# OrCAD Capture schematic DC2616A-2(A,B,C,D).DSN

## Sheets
1 PAGE4: size Custom; title: HIGH EFFICIENCY POLYPHASE STEP-DOWN; rev: 2; company: TM
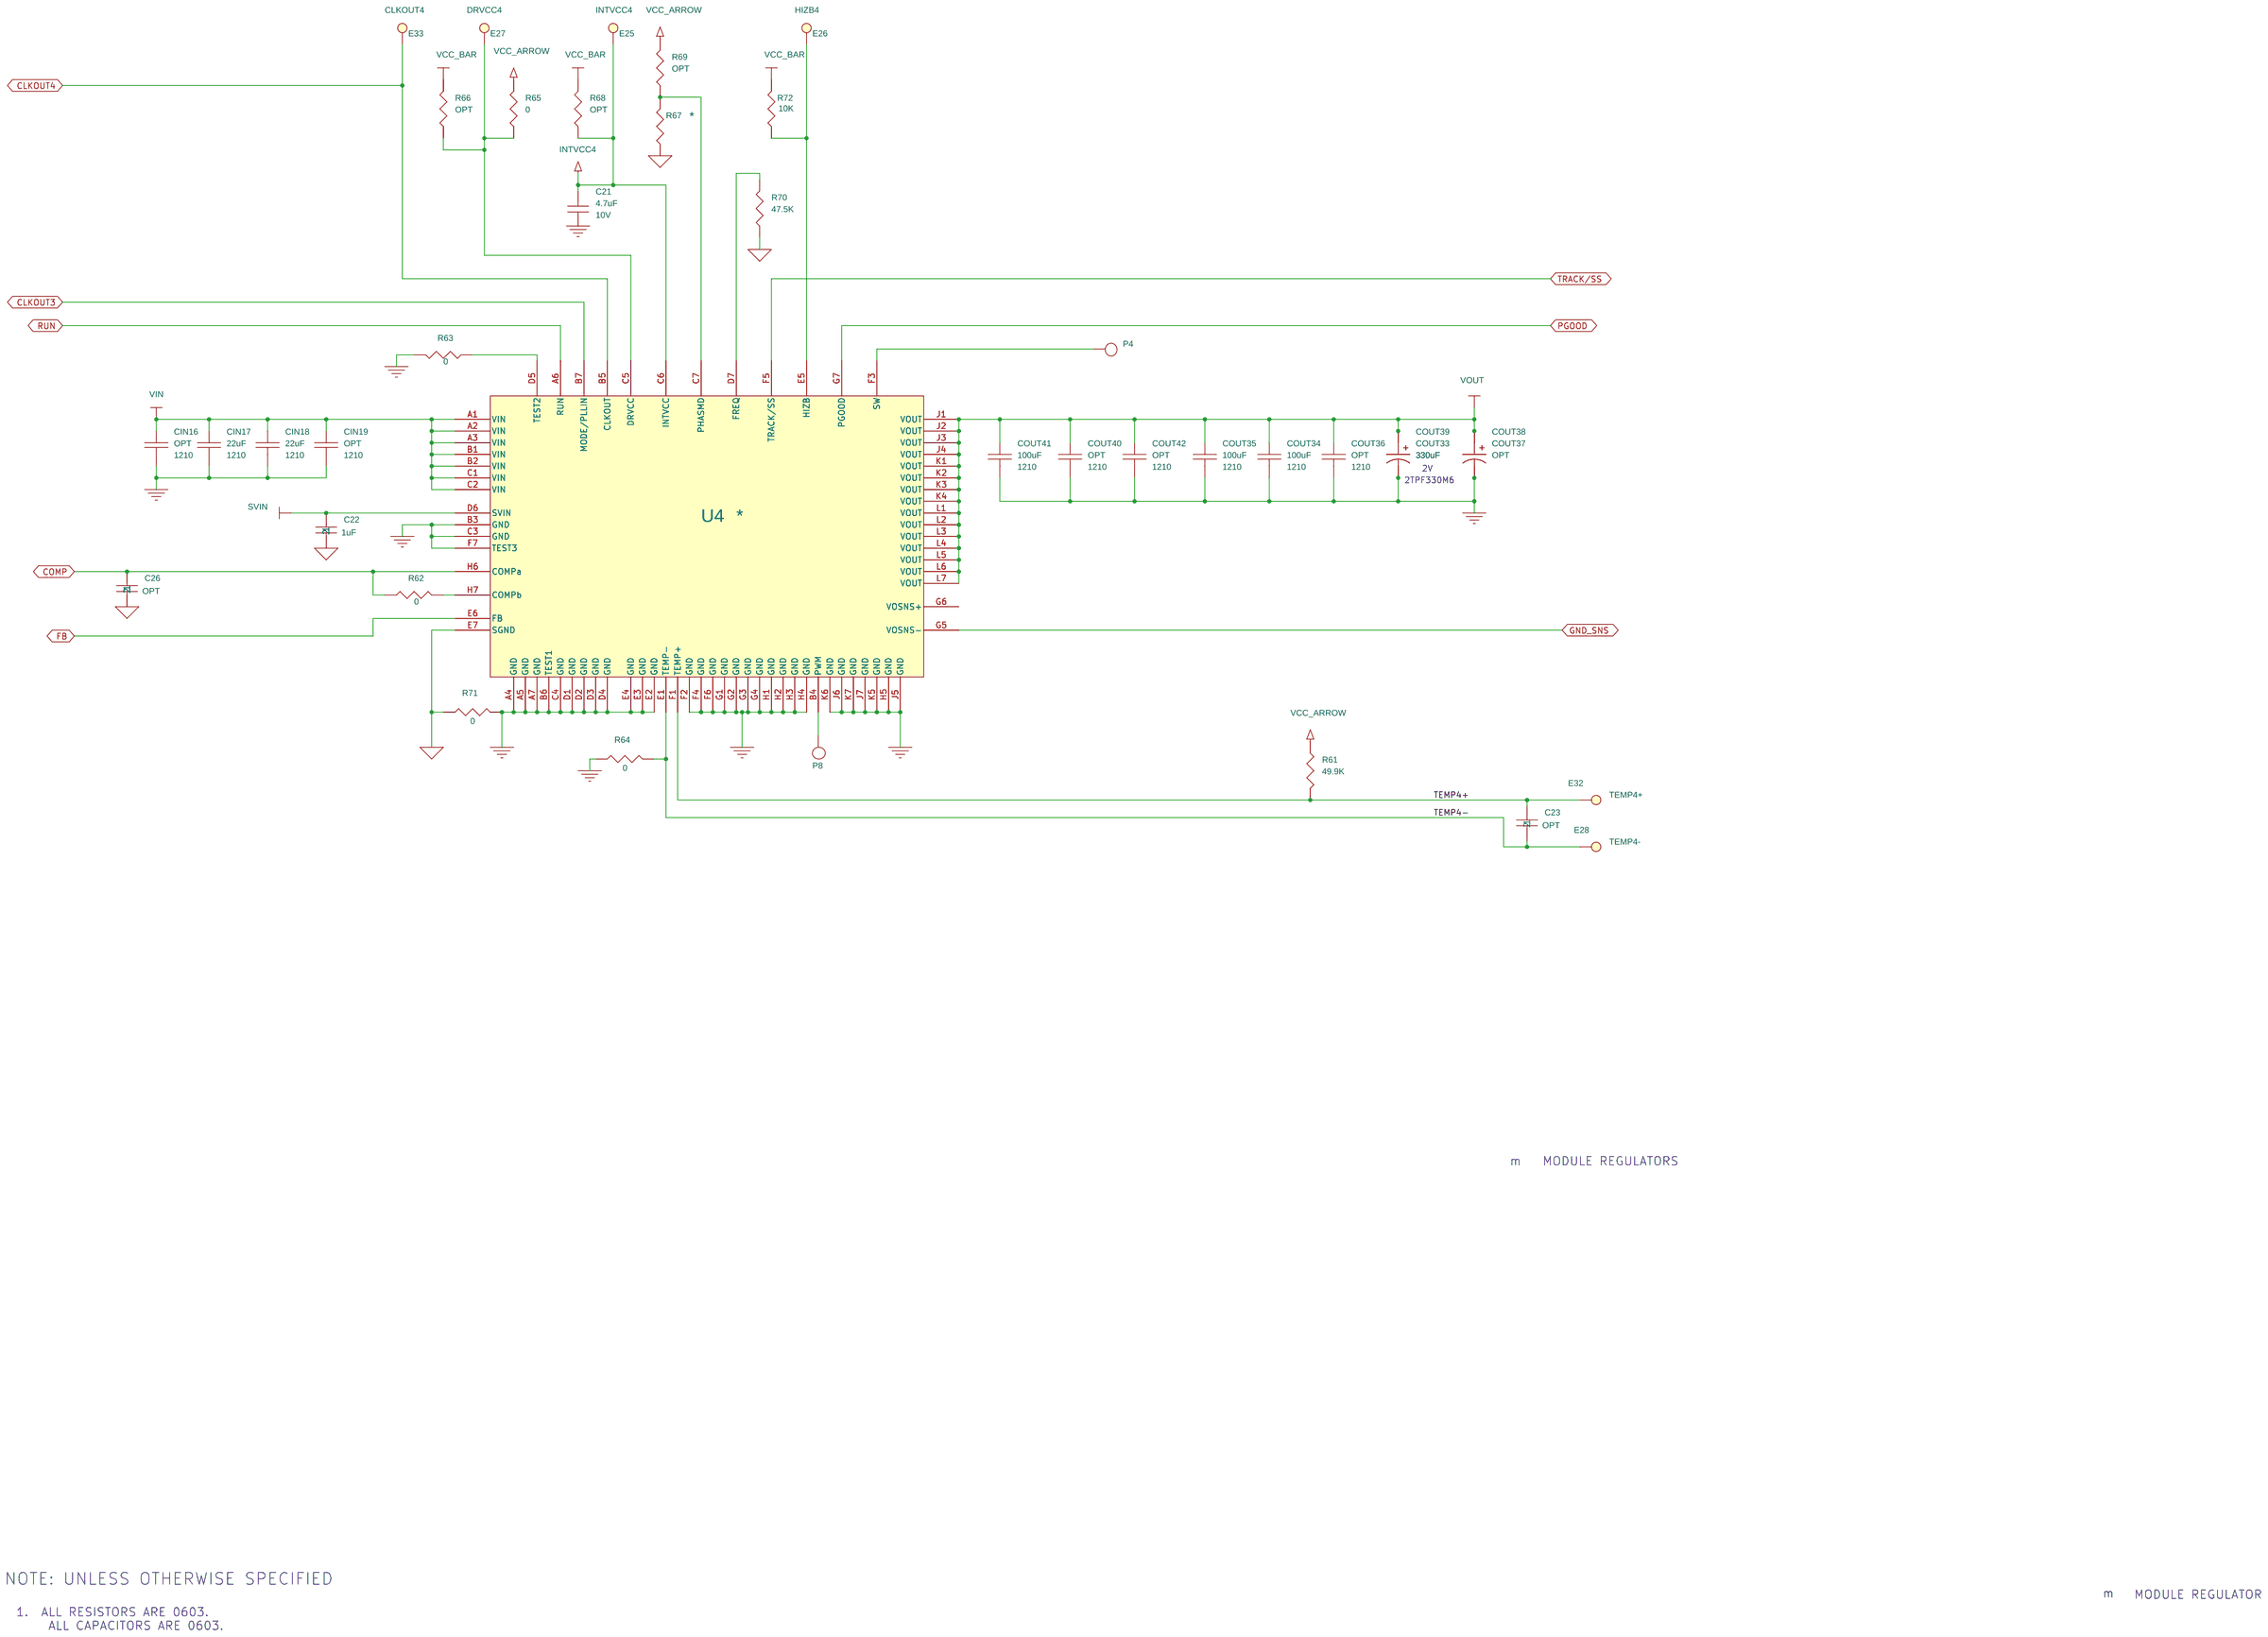
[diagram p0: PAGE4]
2 PAGE3: size Custom
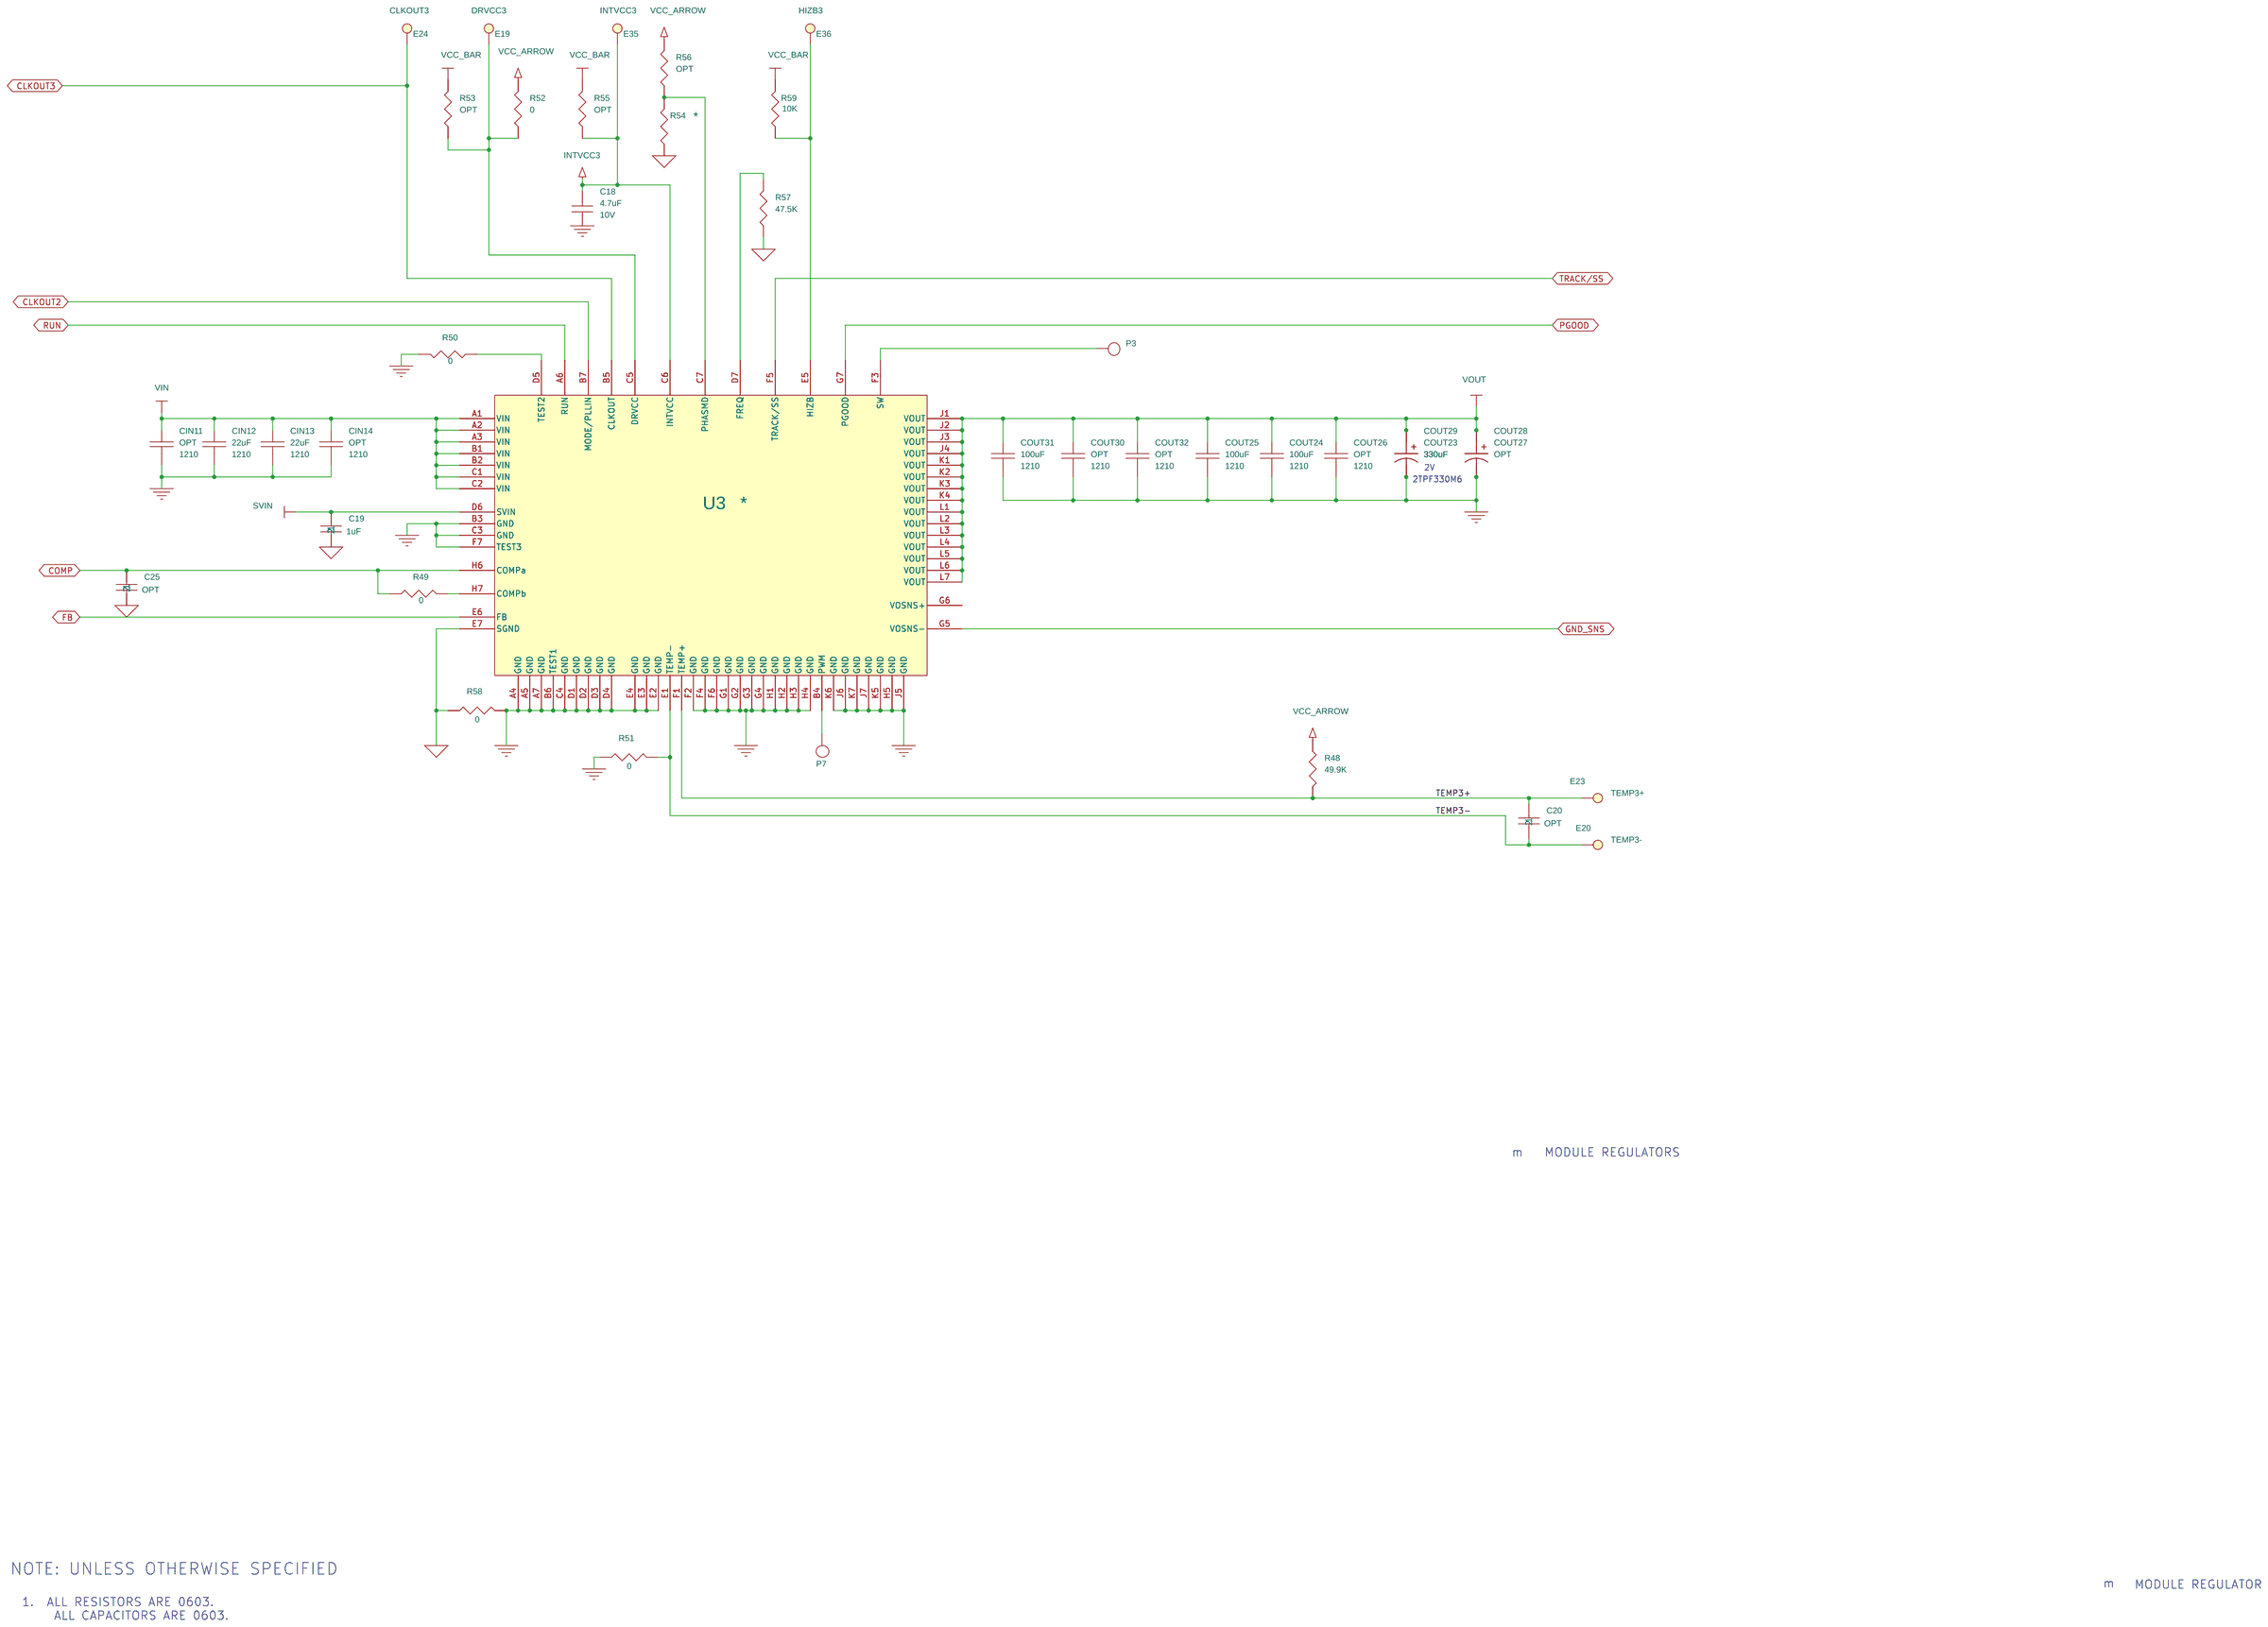
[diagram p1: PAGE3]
3 PAGE2: size Custom
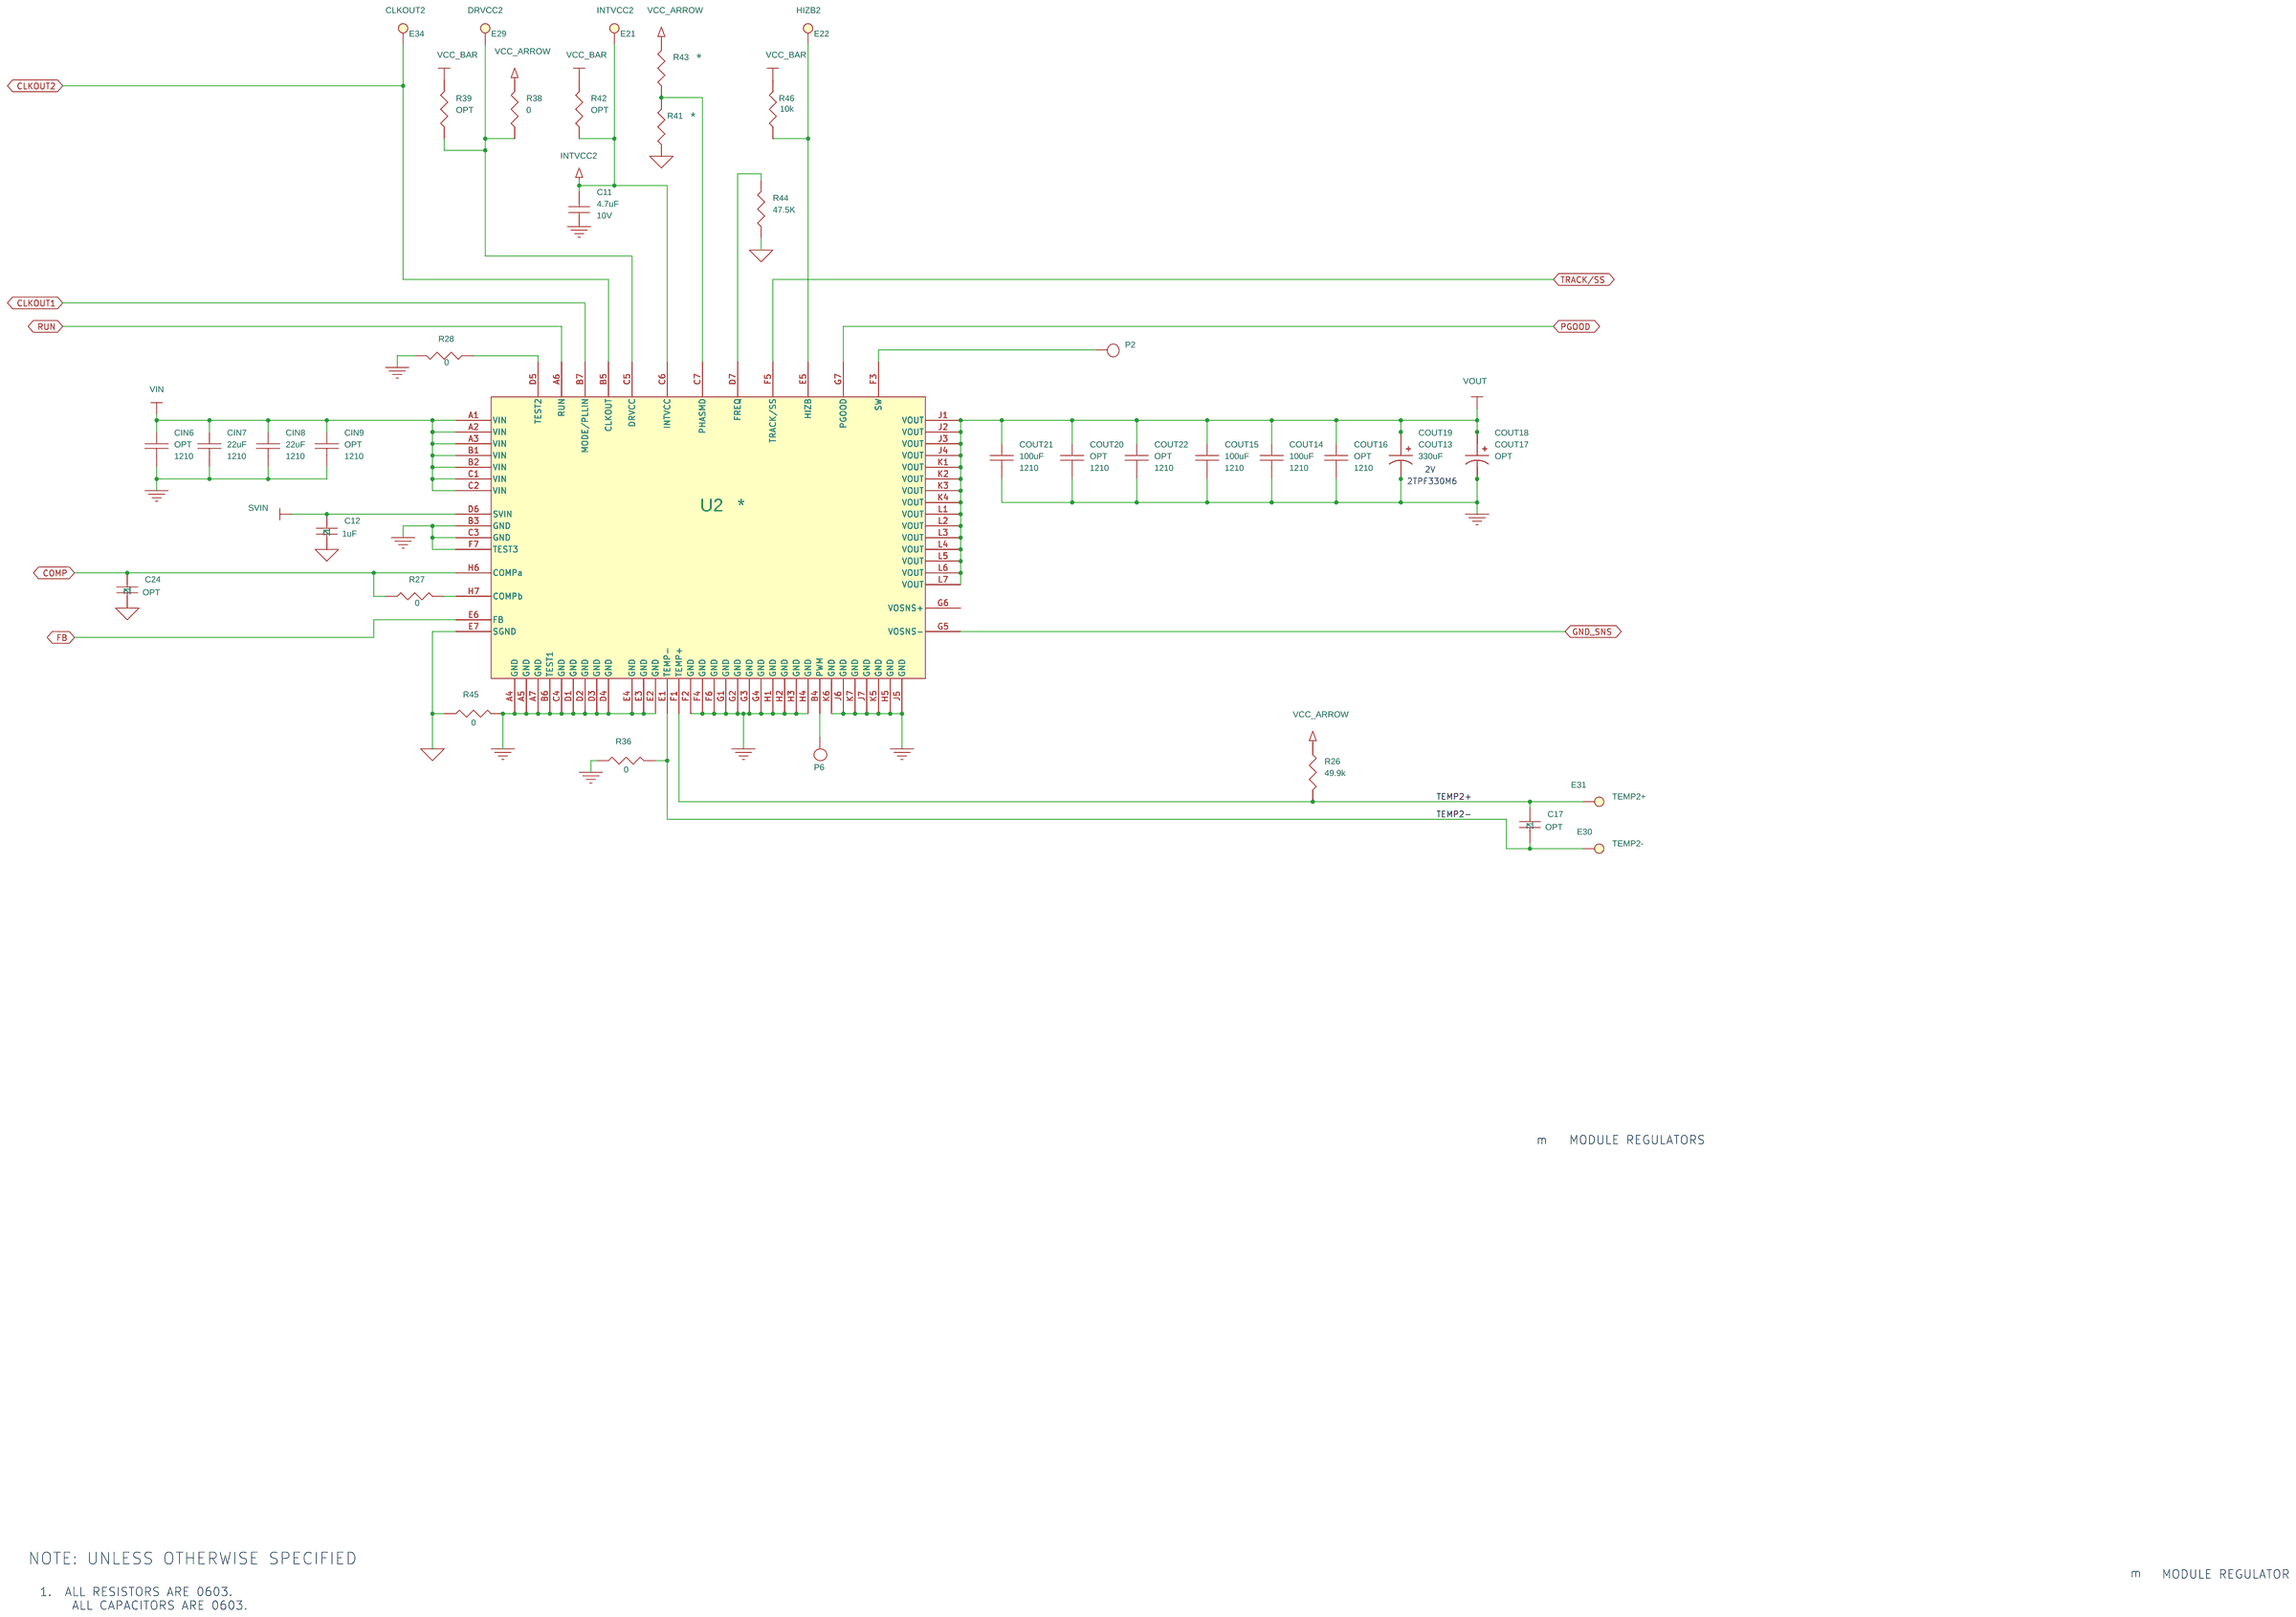
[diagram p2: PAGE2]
4 PAGE1: size Custom
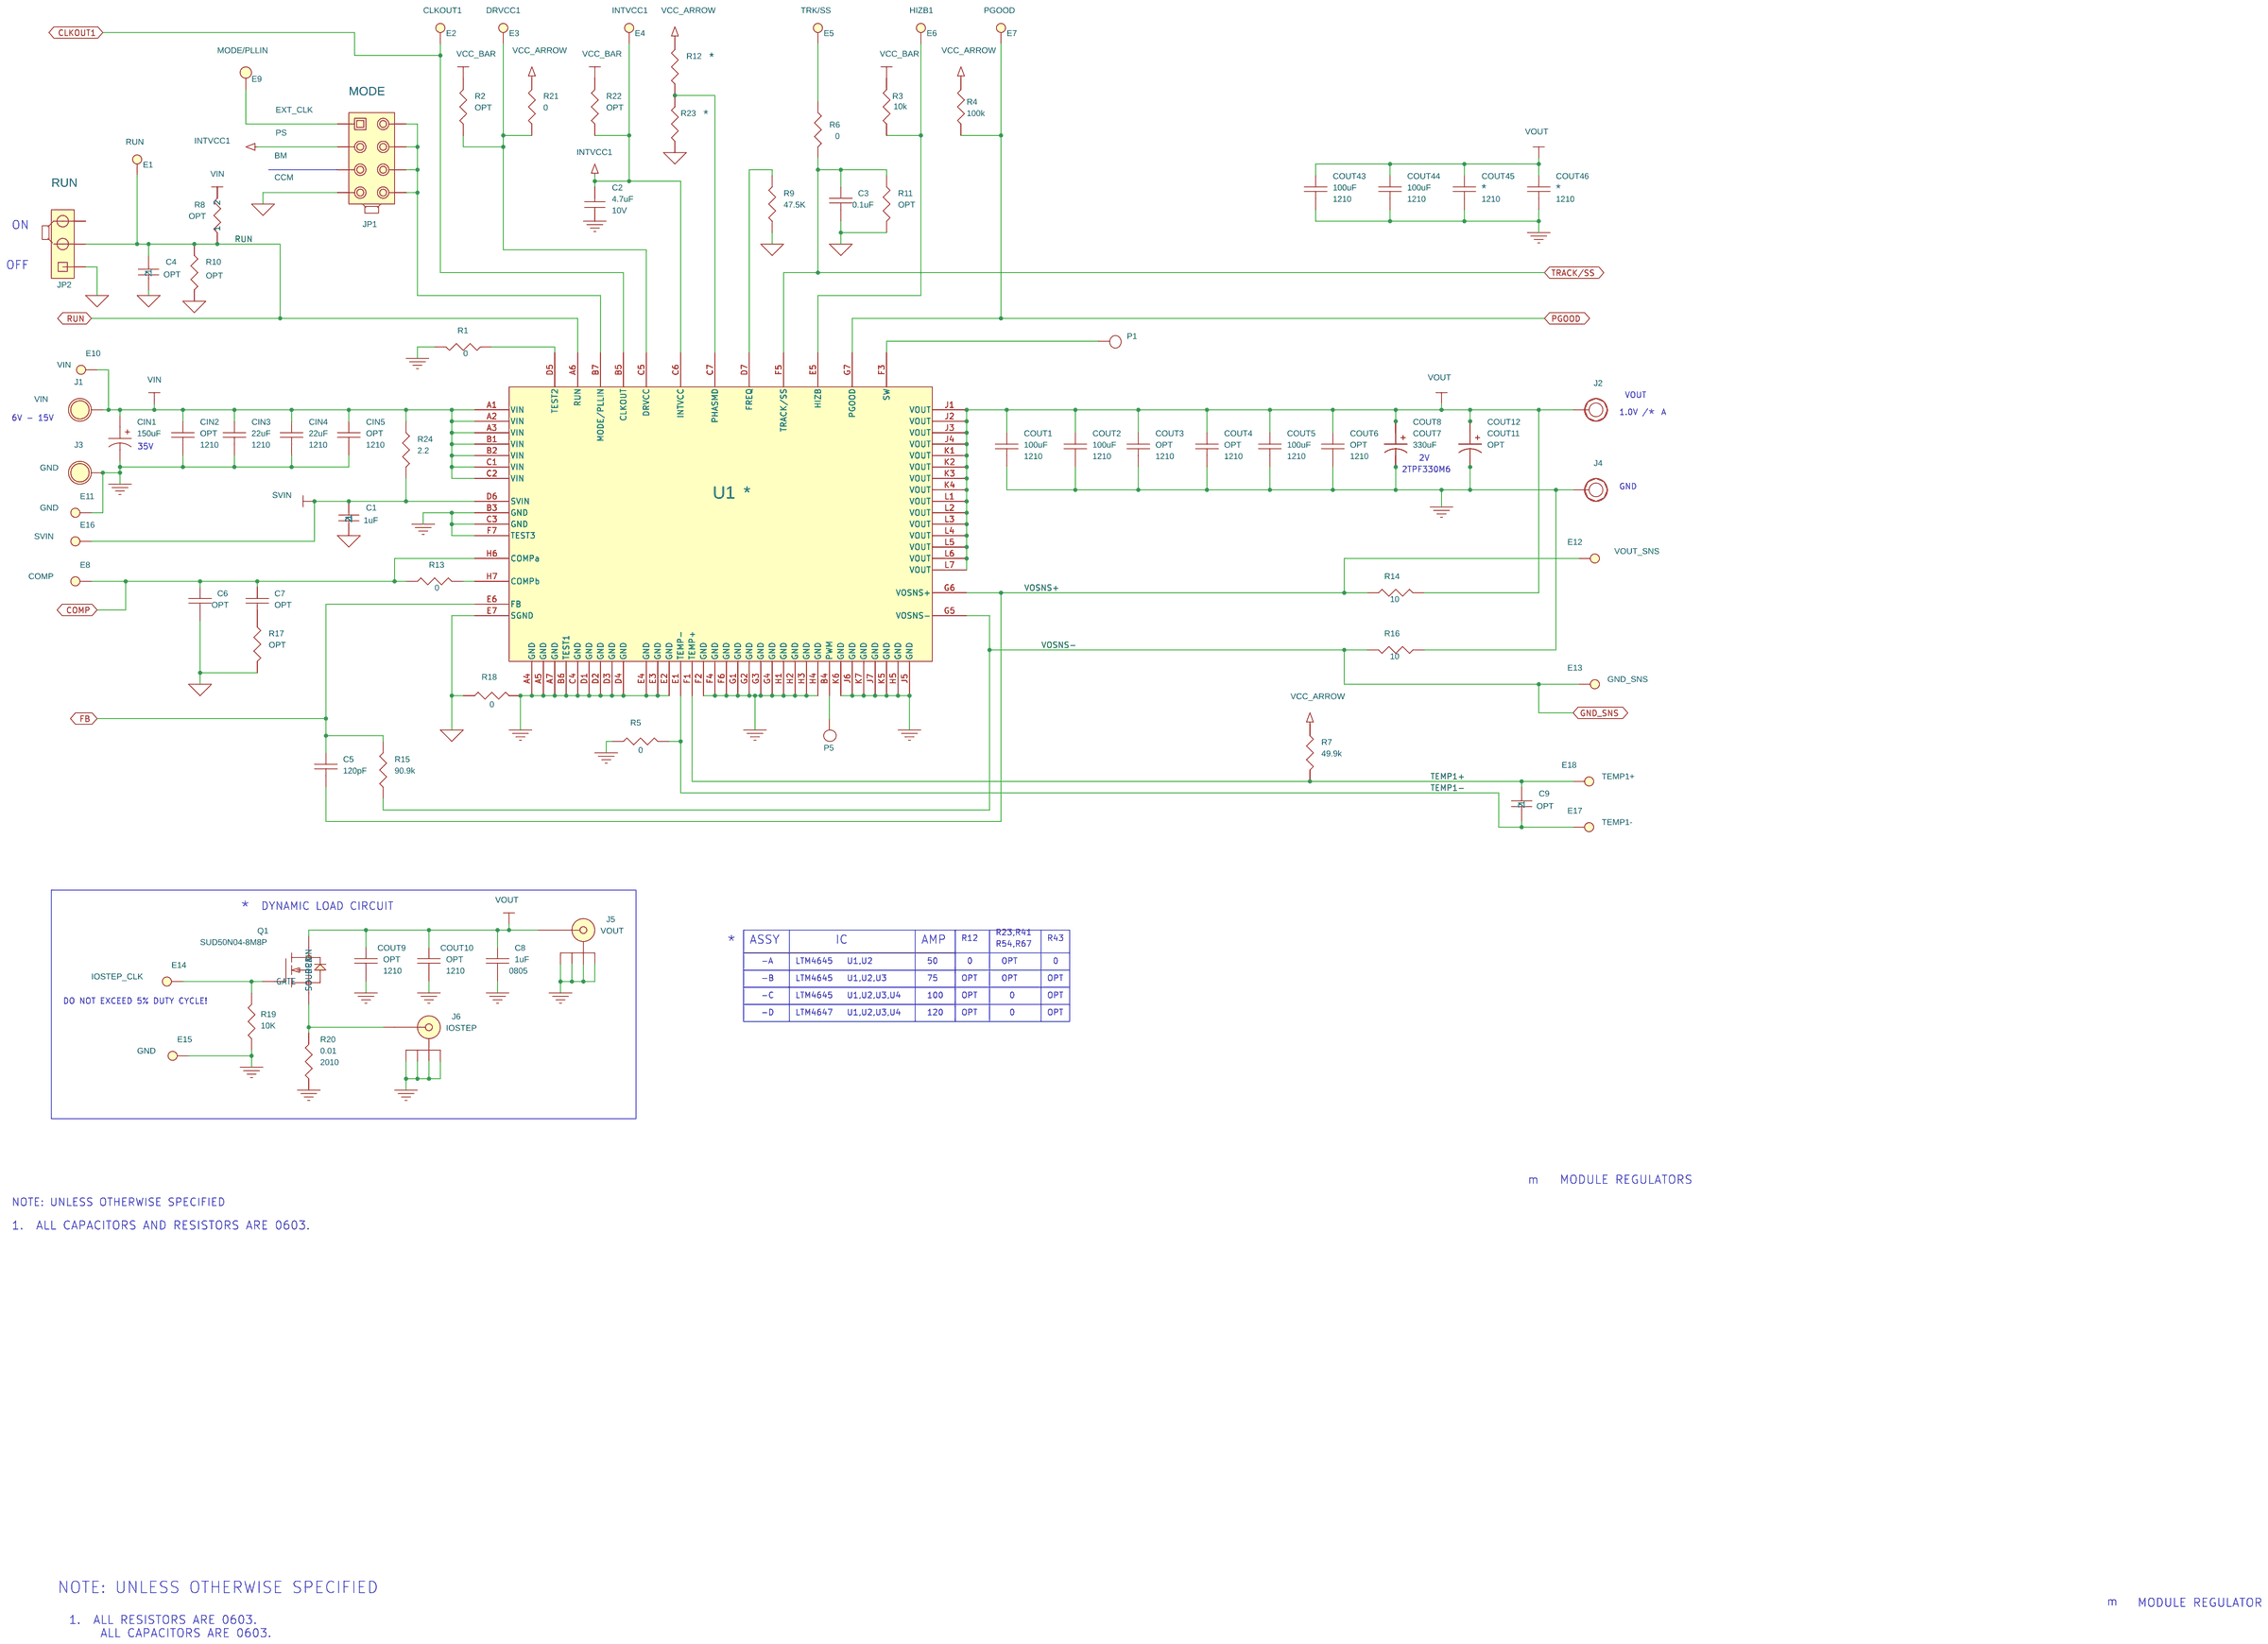
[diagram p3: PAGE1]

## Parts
sheet PAGE1
C1  1uF  [0603]
C2  4.7uF  [0603]
C3  0.1uF  [0603]
C4  OPT  [0603]
C5  120pF  [0603]
C6  OPT  [0603]
C7  OPT  [0603]
C8  1uF  [0805]
C9  OPT  [0603]
CIN1  150uF  [C-10X10.5]
CIN2  OPT  [1210]
CIN3  22uF  [1210]
CIN4  22uF  [1210]
CIN5  OPT  [1210]
COUT1  100uF  [1210]
COUT2  100uF  [1210]
COUT3  OPT  [1210]
COUT4  OPT  [1210]
COUT5  100uF  [1210]
COUT6  OPT  [1210]
COUT7  330uF  [C-D3L-D2E-D4]
COUT8  330uF  [C-D3L-D2E-D4]
COUT9  OPT  [1210]
COUT10  OPT  [1210]
COUT11  OPT  [C-D3L-D2E-D4]
COUT12  OPT  [C-D3L-D2E-D4]
COUT43  100uF  [1210]
COUT44  100uF  [1210]
COUT45  *  [1210]
COUT46  *  [1210]
E1  TURRETS  [MILL-MAX-2308]
E2  CLKOUT1  [MILL-MAX-2308]
E3  DRVCC1  [MILL-MAX-2308]
E4  INTVCC1  [MILL-MAX-2308]
E5  TRK/SS  [MILL-MAX-2308]
E6  HIZB1  [MILL-MAX-2308]
E7  PGOOD  [MILL-MAX-2308]
E8  COMP  [MILL-MAX-2308]
E9  MODE/PLLIN  [MILL-MAX-2308]
E10  TURRETS  [MILL-MAX-2308]
E11  GND  [MILL-MAX-2308]
E12  TURRETS  [MILL-MAX-2308]
E13  TURRETS  [MILL-MAX-2308]
E14  IOSTEP_CLK  [MILL-MAX-2308]
E15  GND  [MILL-MAX-2308]
E16  SVIN  [MILL-MAX-2308]
E17  TURRETS  [MILL-MAX-2308]
E18  TURRETS  [MILL-MAX-2308]
J1  BANANA SMALL  [KEY-575-4]
J2  STUD  [CON\LUG\10]
J3  BANANA SMALL  [KEY-575-4]
J4  STUD  [CON\LUG\10]
J5  VOUT  [BNC]
J6  IOSTEP  [BNC]
JP1  HD2X4-079  [HD2X4-079]
JP2  HD1X3-079  [HD1X3-079]
P1  SMD PAD  [PAD]
P5  SMD PAD  [PAD]
Q1  SUD50N04-8M8P  [TO-252]
R1  0  [0603]
R2  OPT  [0603]
R3  10k  [0603]
R4  100k  [0603]
R5  0  [0603]
R6  0  [0603]
R7  49.9k  [0603]
R8  OPT  [0603]
R9  47.5K  [0603]
R10  OPT  [0603]
R11  OPT  [0603]
R12  *  [0603]
R13  0  [0603]
R14  10  [0603]
R15  90.9k  [0603]
R16  10  [0603]
R17  OPT  [0603]
R18  0  [0603]
R19  10K  [0603]
R20  0.01  [2010]
R21  0  [0603]
R22  OPT  [0603]
R23  *  [0603]
R24  2.2  [0603]
U1  *  [BGA77-15X9-5.01-A]
XJP1  2mm Ctrs.
XJP2  2mm Ctrs.
sheet PAGE2
C11  4.7uF  [0603]
C12  1uF  [0603]
C17  OPT  [0603]
C24  OPT  [0603]
CIN6  OPT  [1210]
CIN7  22uF  [1210]
CIN8  22uF  [1210]
CIN9  OPT  [1210]
COUT13  330uF  [C-D3L-D2E-D4]
COUT14  100uF  [1210]
COUT15  100uF  [1210]
COUT16  OPT  [1210]
COUT17  OPT  [C-D3L-D2E-D4]
COUT18  OPT  [C-D3L-D2E-D4]
COUT19  330uF  [C-D3L-D2E-D4]
COUT20  OPT  [1210]
COUT21  100uF  [1210]
COUT22  OPT  [1210]
E21  INTVCC2  [MILL-MAX-2308]
E22  HIZB2  [MILL-MAX-2308]
E29  DRVCC2  [MILL-MAX-2308]
E30  TURRETS  [MILL-MAX-2308]
E31  TURRETS  [MILL-MAX-2308]
E34  CLKOUT2  [MILL-MAX-2308]
P2  SMD PAD  [PAD]
P6  SMD PAD  [PAD]
R26  49.9k  [0603]
R27  0  [0603]
R28  0  [0603]
R36  0  [0603]
R38  0  [0603]
R39  OPT  [0603]
R41  *  [0603]
R42  OPT  [0603]
R43  *  [0603]
R44  47.5K  [0603]
R45  0  [0603]
R46  10k  [0603]
U2  *  [BGA77-15X9-5.01-A]
sheet PAGE3
C18  4.7uF  [0603]
C19  1uF  [0603]
C20  OPT  [0603]
C25  OPT  [0603]
CIN11  OPT  [1210]
CIN12  22uF  [1210]
CIN13  22uF  [1210]
CIN14  OPT  [1210]
COUT23  330uF  [C-D3L-D2E-D4]
COUT24  100uF  [1210]
COUT25  100uF  [1210]
COUT26  OPT  [1210]
COUT27  OPT  [C-D3L-D2E-D4]
COUT28  OPT  [C-D3L-D2E-D4]
COUT29  330uF  [C-D3L-D2E-D4]
COUT30  OPT  [1210]
COUT31  100uF  [1210]
COUT32  OPT  [1210]
E19  DRVCC3  [MILL-MAX-2308]
E20  TURRETS  [MILL-MAX-2308]
E23  TURRETS  [MILL-MAX-2308]
E24  CLKOUT3  [MILL-MAX-2308]
E35  INTVCC3  [MILL-MAX-2308]
E36  HIZB3  [MILL-MAX-2308]
P3  SMD PAD  [PAD]
P7  SMD PAD  [PAD]
R48  49.9K  [0603]
R49  0  [0603]
R50  0  [0603]
R51  0  [0603]
R52  0  [0603]
R53  OPT  [0603]
R54  *  [0603]
R55  OPT  [0603]
R56  OPT  [0603]
R57  47.5K  [0603]
R58  0  [0603]
R59  10K  [0603]
U3  *  [BGA77-15X9-5.01-A]
sheet PAGE4
C21  4.7uF  [0603]
C22  1uF  [0603]
C23  OPT  [0603]
C26  OPT  [0603]
CIN16  OPT  [1210]
CIN17  22uF  [1210]
CIN18  22uF  [1210]
CIN19  OPT  [1210]
COUT33  330uF  [C-D3L-D2E-D4]
COUT34  100uF  [1210]
COUT35  100uF  [1210]
COUT36  OPT  [1210]
COUT37  OPT  [C-D3L-D2E-D4]
COUT38  OPT  [C-D3L-D2E-D4]
COUT39  330uF  [C-D3L-D2E-D4]
COUT40  OPT  [1210]
COUT41  100uF  [1210]
COUT42  OPT  [1210]
E25  INTVCC4  [MILL-MAX-2308]
E26  HIZB4  [MILL-MAX-2308]
E27  DRVCC4  [MILL-MAX-2308]
E28  TURRETS  [MILL-MAX-2308]
E32  TURRETS  [MILL-MAX-2308]
E33  CLKOUT4  [MILL-MAX-2308]
P4  SMD PAD  [PAD]
P8  SMD PAD  [PAD]
R61  49.9K  [0603]
R62  0  [0603]
R63  0  [0603]
R64  0  [0603]
R65  0  [0603]
R66  OPT  [0603]
R67  *  [0603]
R68  OPT  [0603]
R69  OPT  [0603]
R70  47.5K  [0603]
R71  0  [0603]
R72  10K  [0603]
U4  *  [BGA77-15X9-5.01-A]

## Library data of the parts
C1 C22 C24 C25 = CAP_NP_1: CAP, 0603 0.1uF 10% 50V X7R; Part Number: TDK C1608X7R1H104K; Voltage: 50V
C2 C11 C18 C21 = CAP_NP_3: CAP, 0805 4.7uF 10% 10V X5R; Part Number: TAIYO YUDEN LMK212BJ475KG-T; Voltage: 10V
C3 C5-C7 = CAP0603_1: Component: cap; Manufacturer: TDK; Manufacturer P/N: C1608C0G1H102J; Tolerance: 5%; Type: cer 0603; Vendor: Digikey; Vendor P/N: 445-1293-1-ND; Volts/Amps/Watts: 50V
C4 C17 C19 C23 = CAP_NP_1_1: CAP, 0603 0.1uF 10% 50V X7R; Part Number: TDK C1608X7R1H104K; Voltage: 50V
C8 = CAP0603_1
C9 C12 C20 C26 = CAP_NP_1_2: CAP, 0603 0.1uF 10% 50V X7R; Part Number: TDK C1608X7R1H104K; Voltage: 50V
CIN1 = CAPR12X5_0: Component: cap; Manufacturer: SANYO; Tolerance: 20%; Type: OS-CON; Volts/Amps/Watts: 16V
CIN2-CIN9 CIN11-CIN14 CIN16-CIN19 = CAP1210_1: Component: cap; Manufacturer: Taiyo Yuden; Manufacturer P/N: GMK325BJ106KN-T; Tolerance: 10%; Type: cer 1210; Vendor: Digikey; Vendor P/N: 587-1439-1-ND; Volts/Amps/Watts: 25V
COUT1-COUT6 COUT9 COUT10 COUT14-COUT16 COUT20-COUT22 COUT24-COUT26 COUT30-COUT32 COUT34-COUT36 COUT40-COUT46 = CAP0603_1: Component: cap; Manufacturer: TDK; Manufacturer P/N: C3225X5R0J107M; Part Type: CAP1210; Tolerance: 20%; Type: cer 1210 X5R; Vendor: Digikey; Vendor P/N: 445-1437-1-ND; Volts/Amps/Watts: 6.3v
COUT7 COUT8 COUT11-COUT13 COUT17-COUT19 COUT23 COUT27-COUT29 COUT33 COUT37-COUT39 = CAPR12X5_0: Component: cap; Manufacturer: SANYO; Manufacturer P/N: 6TPF330M9L; Tolerance: 20%; Type: TANT; Volts/Amps/Watts: 6.3V
E1 = TURRETS_1: Component: tp; Label: RUN; Manufacturer: Keystone; Manufacturer P/N: 1593-2; Vendor: Digikey; Vendor P/N: 1593-2K-ND
E2-E8 E14 E16 E19 E21 E22 E24-E27 E29 E33-E36 = TURRETS_1: Component: tp; Label: GND; Manufacturer: Keystone; Manufacturer P/N: 1593-2; Vendor: Digikey; Vendor P/N: 1593-2K-ND
E9 = T_POINT_R_0: TURRET; Part Number: MILL-MAX 2501-2-00-80-00-00-07-0; STATUS: ?
E10 = TURRETS_1: Component: tp; Label: VIN; Manufacturer: Keystone; Manufacturer P/N: 1593-2; Vendor: Digikey; Vendor P/N: 1593-2K-ND
E11 E15 = TURRETS_1: Component: tp; Manufacturer: Keystone; Manufacturer P/N: 1593-2; Vendor: Digikey; Vendor P/N: 1593-2K-ND
E12 = TURRETS_1: Component: tp; Label: VOUT_SNS; Vendor: Digikey; Vendor P/N: 1593-2K-ND
E13 = TURRETS_1: Component: tp; Label: GND_SNS; Vendor: Digikey; Vendor P/N: 1593-2K-ND
E17 = TURRETS_1: Component: tp; Label: TEMP1-; Vendor: Digikey; Vendor P/N: 1593-2K-ND
E18 = TURRETS_1: Component: tp; Label: TEMP1+; Vendor: Digikey; Vendor P/N: 1593-2K-ND
J1 = BANANA_SMALL_0: Component: conn; Label: VIN
J2 J4 = E-KEY-575
J3 = BANANA_SMALL_0: Component: conn; Label: GND
J5 J6 = BNC5-SCH_0
JP1 = Samtec_TMM-103-02-L-D_0: 10th Part Field: PS; 11th Part Field: CCM; 12th Part Field: MODE; 9th Part Field: EXT_CLK; PIN5: BM
JP2 = Commcon2802s03g2_7: 11th Part Field: OFF; 12th Part Field: RUN; 9th Part Field: ON
P1-P8 = PAD_2: Component: tp; Label: <Label>; Vendor: Digikey; Vendor P/N: 1593-2K-ND
Q1 = IRF540_0
R1 R9 R13 R15 R27 R28 R44 R49 R50 R57 R62 R63 R70 = RES0603_9: Manufacturer: Rohm; Manufacturer P/N: RHM0.0GCT-ND; Tolerance: 5%; Vendor: Digikey; Vendor P/N: RHM0.0GCT-ND; Volts/Amps/Watts: 0.1W
R2-R4 R12 R21-R23 R38 R39 R41-R43 R46 R52-R56 R59 R65-R69 R72 = RES_0: RES, 0603 0 OHM JUMPER 1/10W; Part Number: VISHAY CRC06030000Z0EA; Tolerance: JUMPER
R5 R18 R36 R45 R51 R58 R64 R71 = RES0603_3
R6 R7 R11 R17 R24 R26 R48 R61 = RES0603_9: Component: res; Label: <label>; Manufacturer: Panasonic; Manufacturer P/N: ERJ-3EKF5901V; Tolerance: 1%; Vendor: Digikey; Vendor P/N: P5.90KHCT-ND; Volts/Amps/Watts: 0.1W
R8 = CR16-104JM: RES, 0603 30.1k OHMS 1% 1/10W; Part Number: VISHAY CRCW060330K1FKEA
R10 = CR16-2002FM: RES, 0603 10.0k OHMS 1% 1/10W; 5th Part Field: CR16-1002FM; Part Number: VISHAY CRCW060330K1FKEA
R14 = RES0603_9: Manufacturer: Rohm; Manufacturer P/N: MCR03EZPFX1000; Vendor: Digikey; Vendor P/N: RHM100HCT-ND; Volts/Amps/Watts: 0.1W
R16 = RES0603_9: Manufacturer: Yageo; Manufacturer P/N: RC0603JR-070RL; Tolerance: 5%; Vendor: Digikey; Vendor P/N: 311-0.0GRCT-ND; Volts/Amps/Watts: 0.1W
R19 = RES0603_9
R20 = RES0603_5: Label: 1W; Manufacturer: VISHAY; Manufacturer P/N: CRCW251230R0JNEG; Part Type: 2512; Tolerance: 5%; Vendor: Digikey; Vendor P/N: 541-30XCT-ND; Volts/Amps/Watts: 0.1W
U1-U4 = LTC3880-M0001_52: Component: IC; Manufacturer: LTC; Manufacturer P/N: LTC3880_M0001; Vendor: LTC; Vendor P/N: LTC3880_M0001
XJP1 XJP2 = CommconCCIJ2MM-138G
E30 = TURRETS_1: Component: tp; Label: TEMP2-; Vendor: Digikey; Vendor P/N: 1593-2K-ND
E31 = TURRETS_1: Component: tp; Label: TEMP2+; Vendor: Digikey; Vendor P/N: 1593-2K-ND
E20 = TURRETS_1: Component: tp; Label: TEMP3-; Vendor: Digikey; Vendor P/N: 1593-2K-ND
E23 = TURRETS_1: Component: tp; Label: TEMP3+; Vendor: Digikey; Vendor P/N: 1593-2K-ND
E28 = TURRETS_1: Component: tp; Label: TEMP4-; Vendor: Digikey; Vendor P/N: 1593-2K-ND
E32 = TURRETS_1: Component: tp; Label: TEMP4+; Vendor: Digikey; Vendor P/N: 1593-2K-ND

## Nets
GND_POWER: C2.2 C8.2 C11.2 C18.2 C21.2 CIN1.2 CIN2.2 CIN3.2 CIN4.2 CIN5.2 CIN6.2 CIN7.2 CIN8.2 CIN9.2 CIN11.2 CIN12.2 CIN13.2 CIN14.2 CIN16.2 CIN17.2 CIN18.2 CIN19.2 COUT1.2 COUT2.2 COUT3.2 COUT4.2 COUT5.2 COUT6.2 COUT7.2 COUT8.2 COUT9.2 COUT10.2 COUT11.2 COUT12.2 COUT13.2 COUT14.2 COUT15.2 COUT16.2 COUT17.2 COUT18.2 COUT19.2 COUT20.2 COUT21.2 COUT22.2 COUT23.2 COUT24.2 COUT25.2 COUT26.2 COUT27.2 COUT28.2 COUT29.2 COUT30.2 COUT31.2 COUT32.2 COUT33.2 COUT34.2 COUT35.2 COUT36.2 COUT37.2 COUT38.2 COUT39.2 COUT40.2 COUT41.2 COUT42.2 COUT43.2 COUT44.2 COUT45.2 COUT46.2 E11.1(TP) E15.1(TP) J3.1(TP) J4.1 J5.2 J5.3 J5.4 J5.5 J6.2 J6.3 J6.4 J6.5 R1.2 R5.1 R16.2 R18.2 R19.2 R20.1 R28.2 R36.1 R45.2 R50.2 R51.1 R58.2 R63.2 R64.1 R71.2 U1.A4(GND) U1.A5(GND) U1.A7(GND) U1.B3(GND) U1.B6(TEST1) U1.C3(GND) U1.C4(GND) U1.D1(GND) U1.D2(GND) U1.D3(GND) U1.D4(GND) U1.E2(GND) U1.E3(GND) U1.E4(GND) U1.F2(GND) U1.F4(GND) U1.F6(GND) U1.F7(TEST3) U1.G1(GND) U1.G2(GND) U1.G3(GND) U1.G4(GND) U1.H1(GND) U1.H2(GND) U1.H3(GND) U1.H4(GND) U1.H5(GND) U1.J5(GND) U1.J6(GND) U1.J7(GND) U1.K5(GND) U1.K6(GND) U1.K7(GND) U2.A4(GND) U2.A5(GND) U2.A7(GND) U2.B3(GND) U2.B6(TEST1) U2.C3(GND) U2.C4(GND) U2.D1(GND) U2.D2(GND) U2.D3(GND) U2.D4(GND) U2.E2(GND) U2.E3(GND) U2.E4(GND) U2.F2(GND) U2.F4(GND) U2.F6(GND) U2.F7(TEST3) U2.G1(GND) U2.G2(GND) U2.G3(GND) U2.G4(GND) U2.H1(GND) U2.H2(GND) U2.H3(GND) U2.H4(GND) U2.H5(GND) U2.J5(GND) U2.J6(GND) U2.J7(GND) U2.K5(GND) U2.K6(GND) U2.K7(GND) U3.A4(GND) U3.A5(GND) U3.A7(GND) U3.B3(GND) U3.B6(TEST1) U3.C3(GND) U3.C4(GND) U3.D1(GND) U3.D2(GND) U3.D3(GND) U3.D4(GND) U3.E2(GND) U3.E3(GND) U3.E4(GND) U3.F2(GND) U3.F4(GND) U3.F6(GND) U3.F7(TEST3) U3.G1(GND) U3.G2(GND) U3.G3(GND) U3.G4(GND) U3.H1(GND) U3.H2(GND) U3.H3(GND) U3.H4(GND) U3.H5(GND) U3.J5(GND) U3.J6(GND) U3.J7(GND) U3.K5(GND) U3.K6(GND) U3.K7(GND) U4.A4(GND) U4.A5(GND) U4.A7(GND) U4.B3(GND) U4.B6(TEST1) U4.C3(GND) U4.C4(GND) U4.D1(GND) U4.D2(GND) U4.D3(GND) U4.D4(GND) U4.E2(GND) U4.E3(GND) U4.E4(GND) U4.F2(GND) U4.F4(GND) U4.F6(GND) U4.F7(TEST3) U4.G1(GND) U4.G2(GND) U4.G3(GND) U4.G4(GND) U4.H1(GND) U4.H2(GND) U4.H3(GND) U4.H4(GND) U4.H5(GND) U4.J5(GND) U4.J6(GND) U4.J7(GND) U4.K5(GND) U4.K6(GND) U4.K7(GND)
GND_SIGNAL: C1.2 C3.2 C4.2 C6.2 C12.2 C19.2 C22.2 C24.2 C25.2 C26.2 JP1.7 JP2.1 R9.2 R10.2 R11.2 R17.2 R18.1 R23.2 R41.2 R44.2 R45.1 R54.2 R57.2 R58.1 R67.2 R70.2 R71.1 U1.E7(SGND) U2.E7(SGND) U3.E7(SGND) U4.E7(SGND)
GND_SNS: E13.1(TP) R15.1 R16.1 U1.G5(VOSNS-) U2.G5(VOSNS-) U3.G5(VOSNS-) U4.G5(VOSNS-)
SVIN: C1.1 C12.1 C19.1 C22.1 E16.1(TP) R22.1 R24.2 R42.1 R55.1 R68.1 U1.D6(SVIN) U2.D6(SVIN) U3.D6(SVIN) U4.D6(SVIN)
VIN: CIN1.1 CIN2.1 CIN3.1 CIN4.1 CIN5.1 CIN6.1 CIN7.1 CIN8.1 CIN9.1 CIN11.1 CIN12.1 CIN13.1 CIN14.1 CIN16.1 CIN17.1 CIN18.1 CIN19.1 E10.1(TP) J1.1(TP) R2.1 R3.1 R8.2 R24.1 R39.1 R46.1 R53.1 R59.1 R66.1 R72.1 U1.A1(VIN) U1.A2(VIN) U1.A3(VIN) U1.B1(VIN) U1.B2(VIN) U1.C1(VIN) U1.C2(VIN) U2.A1(VIN) U2.A2(VIN) U2.A3(VIN) U2.B1(VIN) U2.B2(VIN) U2.C1(VIN) U2.C2(VIN) U3.A1(VIN) U3.A2(VIN) U3.A3(VIN) U3.B1(VIN) U3.B2(VIN) U3.C1(VIN) U3.C2(VIN) U4.A1(VIN) U4.A2(VIN) U4.A3(VIN) U4.B1(VIN) U4.B2(VIN) U4.C1(VIN) U4.C2(VIN)
CLKOUT1: E2.1(TP) U1.B5(CLKOUT) U2.B7(MODE/PLLIN)
CLKOUT2: E34.1(TP) U2.B5(CLKOUT) U3.B7(MODE/PLLIN)
CLKOUT3: E24.1(TP) U3.B5(CLKOUT) U4.B7(MODE/PLLIN)
CLKOUT4: E33.1(TP) U4.B5(CLKOUT)
COMP: C6.1 C7.1 C24.1 C25.1 C26.1 E8.1(TP) R13.2 R27.2 R49.2 R62.2 U1.H6(COMPa) U2.H6(COMPa) U3.H6(COMPa) U4.H6(COMPa)
FB: C5.1 R15.2 U1.E6(FB) U2.E6(FB) U3.E6(FB) U4.E6(FB)
INTVCC1: C2.1 E4.1(TP) JP1.3 R4.1 R7.1 R12.1 R21.1 R22.2 U1.C6(INTVCC)
INTVCC2: C11.1 E21.1(TP) R26.1 R38.1 R42.2 R43.1 U2.C6(INTVCC)
INTVCC3: C18.1 E35.1(TP) R48.1 R52.1 R55.2 R56.1 U3.C6(INTVCC)
INTVCC4: C21.1 E25.1(TP) R61.1 R65.1 R68.2 R69.1 U4.C6(INTVCC)
PGOOD: E7.1(TP) R4.2 U1.G7(PGOOD) U2.G7(PGOOD) U3.G7(PGOOD) U4.G7(PGOOD)
RUN: C4.1 E1.1(TP) JP2.2 R8.1 R10.1 U1.A6(RUN) U2.A6(RUN) U3.A6(RUN) U4.A6(RUN)
TEMP1+: C9.1 E18.1(TP) R7.2 U1.F1(TEMP+)
TEMP1-: C9.2 E17.1(TP) R5.2 U1.E1(TEMP-)
TEMP2+: C17.1 E31.1(TP) R26.2 U2.F1(TEMP+)
TEMP2-: C17.2 E30.1(TP) R36.2 U2.E1(TEMP-)
TEMP3+: C20.1 E23.1(TP) R48.2 U3.F1(TEMP+)
TEMP3-: C20.2 E20.1(TP) R51.2 U3.E1(TEMP-)
TEMP4+: C23.1 E32.1(TP) R61.2 U4.F1(TEMP+)
TEMP4-: C23.2 E28.1(TP) R64.2 U4.E1(TEMP-)
TRACK/SS: C3.1 R6.2 R11.1 U1.F5(TRACK/SS) U2.F5(TRACK/SS) U3.F5(TRACK/SS) U4.F5(TRACK/SS)
VOSNS+: C5.2 E12.1(TP) R14.1 U1.G6(VOSNS+)
VOUT: C8.1 COUT1.1 COUT2.1 COUT3.1 COUT4.1 COUT5.1 COUT6.1 COUT7.1 COUT8.1 COUT9.1 COUT10.1 COUT11.1 COUT12.1 COUT13.1 COUT14.1 COUT15.1 COUT16.1 COUT17.1 COUT18.1 COUT19.1 COUT20.1 COUT21.1 COUT22.1 COUT23.1 COUT24.1 COUT25.1 COUT26.1 COUT27.1 COUT28.1 COUT29.1 COUT30.1 COUT31.1 COUT32.1 COUT33.1 COUT34.1 COUT35.1 COUT36.1 COUT37.1 COUT38.1 COUT39.1 COUT40.1 COUT41.1 COUT42.1 COUT43.1 COUT44.1 COUT45.1 COUT46.1 J2.1 J5.1 Q1.2(DRAIN) R14.2 U1.J1(VOUT) U1.J2(VOUT) U1.J3(VOUT) U1.J4(VOUT) U1.K1(VOUT) U1.K2(VOUT) U1.K3(VOUT) U1.K4(VOUT) U1.L1(VOUT) U1.L2(VOUT) U1.L3(VOUT) U1.L4(VOUT) U1.L5(VOUT) U1.L6(VOUT) U1.L7(VOUT) U2.J1(VOUT) U2.J2(VOUT) U2.J3(VOUT) U2.J4(VOUT) U2.K1(VOUT) U2.K2(VOUT) U2.K3(VOUT) U2.K4(VOUT) U2.L1(VOUT) U2.L2(VOUT) U2.L3(VOUT) U2.L4(VOUT) U2.L5(VOUT) U2.L6(VOUT) U2.L7(VOUT) U3.J1(VOUT) U3.J2(VOUT) U3.J3(VOUT) U3.J4(VOUT) U3.K1(VOUT) U3.K2(VOUT) U3.K3(VOUT) U3.K4(VOUT) U3.L1(VOUT) U3.L2(VOUT) U3.L3(VOUT) U3.L4(VOUT) U3.L5(VOUT) U3.L6(VOUT) U3.L7(VOUT) U4.J1(VOUT) U4.J2(VOUT) U4.J3(VOUT) U4.J4(VOUT) U4.K1(VOUT) U4.K2(VOUT) U4.K3(VOUT) U4.K4(VOUT) U4.L1(VOUT) U4.L2(VOUT) U4.L3(VOUT) U4.L4(VOUT) U4.L5(VOUT) U4.L6(VOUT) U4.L7(VOUT)
N17002004: C7.2 R17.1
N18445914: E14.1(TP) Q1.1(GATE) R19.1
N18446004: J6.1 Q1.3(SOURCE) R20.2
N18545248: JP1.2 JP1.4 JP1.6 JP1.8 U1.B7(MODE/PLLIN)
N18614805: E6.1(TP) R3.2 U1.E5(HIZB)
N18638855: R12.2 R23.1 U1.C7(PHASMD)
N18652648: P1.1(TP) U1.F3(SW)
N18664179: R13.1 U1.H7(COMPb)
N18764356: E9.1(TP) JP1.1
N18853132: R9.1 U1.D7(FREQ)
N18884741: E5.1(TP) R6.1
N19032140: P5.1(TP) U1.B4(PWM)
N19072015: E3.1(TP) R2.2 R21.2 U1.C5(DRVCC)
N19201331: R1.1 U1.D5(TEST2)
N19217400: P2.1(TP) U2.F3(SW)
N19217470: E22.1(TP) R46.2 U2.E5(HIZB)
N19217894: P6.1(TP) U2.B4(PWM)
N19217958: R28.1 U2.D5(TEST2)
N19217968: E29.1(TP) R38.2 R39.2 U2.C5(DRVCC)
N19218121: R44.1 U2.D7(FREQ)
N19218596: R41.1 R43.2 U2.C7(PHASMD)
N19218612: R27.1 U2.H7(COMPb)
N19224492: P3.1(TP) U3.F3(SW)
N19224540: E36.1(TP) R59.2 U3.E5(HIZB)
N19224879: P7.1(TP) U3.B4(PWM)
N19224902: R50.1 U3.D5(TEST2)
N19224912: E19.1(TP) R52.2 R53.2 U3.C5(DRVCC)
N19224976: R57.1 U3.D7(FREQ)
N19225229: R54.1 R56.2 U3.C7(PHASMD)
N19225236: R49.1 U3.H7(COMPb)
N19226514: P4.1(TP) U4.F3(SW)
N19226562: E26.1(TP) R72.2 U4.E5(HIZB)
N19226901: P8.1(TP) U4.B4(PWM)
N19226924: R63.1 U4.D5(TEST2)
N19226934: E27.1(TP) R65.2 R66.2 U4.C5(DRVCC)
N19226998: R70.1 U4.D7(FREQ)
N19227251: R67.1 R69.2 U4.C7(PHASMD)
N19227258: R62.1 U4.H7(COMPb)

Not connected (* = marked no-connect by the designer): JP1 5; JP2 3; U2 G6(VOSNS+); U3 G6(VOSNS+); U4 G6(VOSNS+)

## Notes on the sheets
sheet 1
- 2V
- 2TPF330M6
- MODULE REGULATORS
- m
- NOTE: UNLESS OTHERWISE SPECIFIED
- MODULE REGULATOR
- m
- 1.  ALL RESISTORS ARE 0603.
       ALL CAPACITORS ARE 0603.
sheet 2
- 2TPF330M6
- 2V
- MODULE REGULATORS
- m
- NOTE: UNLESS OTHERWISE SPECIFIED
- MODULE REGULATOR
- m
- 1.  ALL RESISTORS ARE 0603.
       ALL CAPACITORS ARE 0603.
sheet 3
- 2V
- 2TPF330M6
- MODULE REGULATORS
- m
- NOTE: UNLESS OTHERWISE SPECIFIED
- MODULE REGULATOR
- m
- 1.  ALL RESISTORS ARE 0603.
       ALL CAPACITORS ARE 0603.
sheet 4
- ON
- OFF
- VOUT
- 6V - 15V
- 1.0V /   A
- *
- 35V
- 2V
- 2TPF330M6
- GND
- *
- DYNAMIC LOAD CIRCUIT
- R23,R41
- *
- ASSY
- IC
- AMP
- R12
- R54,R67
- R43
- -A
- LTM4645
- U1,U2
- 50
- 0
- OPT
- 0
- -B
- LTM4645
- U1,U2,U3
- 75
- OPT
- OPT
- OPT
- DO NOT EXCEED 5% DUTY CYCLE!
- -C
- LTM4645
- U1,U2,U3,U4
- 100
- OPT
- 0
- OPT
- -D
- LTM4647
- U1,U2,U3,U4
- 120
- OPT
- 0
- OPT
- MODULE REGULATORS
- m
- NOTE: UNLESS OTHERWISE SPECIFIED
- 1.  ALL CAPACITORS AND RESISTORS ARE 0603.
- NOTE: UNLESS OTHERWISE SPECIFIED
- MODULE REGULATOR
- m
- 1.  ALL RESISTORS ARE 0603.
       ALL CAPACITORS ARE 0603.
